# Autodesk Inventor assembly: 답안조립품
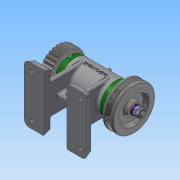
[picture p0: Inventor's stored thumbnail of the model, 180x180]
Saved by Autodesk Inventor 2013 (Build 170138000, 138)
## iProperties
Created: 2016-07
Part Number: 답안조립품
Document SubType Name: Assembly
Designer: Administrator
Author: Administrator
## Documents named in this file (16)
- C:\Users\Administrator\Desktop\460708V1020\답안조립품.iam
- C:\Users\Administrator\Desktop\460708V1020\본체.ipt
- C:\Users\Administrator\Desktop\460708V1020\V벨트풀리.ipt
- C:\Users\Administrator\Desktop\460708V1020\너트 M 8.ipt
- C:\Users\Administrator\Desktop\460708V1020\니플 M 6 x 0.75.ipt
- C:\Users\Administrator\Desktop\460708V1020\베어링 15 x 32 x 9.ipt
- C:\Users\Administrator\Desktop\460708V1020\볼트 M 6 x 8.ipt
- C:\Users\Administrator\Desktop\460708V1020\볼트 M4 x 12.ipt
- C:\Users\Administrator\Desktop\460708V1020\스퍼기어.ipt
- C:\Users\Administrator\Desktop\460708V1020\스프링와셔 8.ipt
- C:\Users\Administrator\Desktop\460708V1020\오일 실 15 25 7.ipt
- C:\Users\Administrator\Desktop\460708V1020\와셔 6x11.5.ipt
- C:\Users\Administrator\Desktop\460708V1020\와셔 8x17.ipt
- C:\Users\Administrator\Desktop\460708V1020\축.ipt
- C:\Users\Administrator\Desktop\460708V1020\커버.ipt
- C:\Users\Administrator\Desktop\460708V1020\키 3 x 3 x 12.ipt
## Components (11 placed, 3 different names)
1. V벨트풀리:1
2. KS B 2023 6002 - 15 x 32 x 9:1
3. KS B 2023 6002 - 15 x 32 x 9:2
4. ISO 4762 M4 x 12:2
5. ISO 4762 M4 x 12:3
6. ISO 4762 M4 x 12:4
7. ISO 4762 M4 x 12:5
8. ISO 4762 M4 x 12:1
9. ISO 4762 M4 x 12:6
10. ISO 4762 M4 x 12:7
11. ISO 4762 M4 x 12:8
